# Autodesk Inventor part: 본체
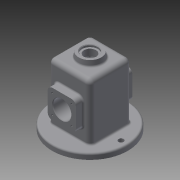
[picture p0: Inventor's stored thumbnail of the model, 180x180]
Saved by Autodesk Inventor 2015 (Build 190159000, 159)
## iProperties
Created: 2021-08
Part Number: 본체
Material: 일반
Document SubType Name: Modeling
Designer: 104589
Density: 1 g/cm^3
Appearance: 기본값
Mass: 304.335 g
Surface Area: 949.017 cm^2
Volume: 304.335 cm^3
Author: 104589
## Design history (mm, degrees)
sketch "스케치1"
  geometry: L1 (-37, -37)-(37, -37); L2 (37, -37)-(37, 37); L3 (37, 37)-(-37, 37); L4 (-37, 37)-(-37, -37); L5 (-37, -37)-(37, 37); L6 (37, -37)-(-37, 37); 1 further point
  constraints: 12 end point, 2 midpoint, 2 parallel, 1 horizontal, 1 perpendicular
  dimensions: "d0" = 74 distance of L2.end L3.end; "d1" = 74 distance of L1.end L2.end
extrude "돌출1" new body sketch "스케치1" distance "d2" = 100; taper "d3" = 0 deg
fillet "모깎기1" dims "d4" = 8
fillet "모깎기2" dims "d5" = 8
feature "쉘1" dims "d6" = 5
sketch "스케치3"
  geometry: L1 (-29, 32)-(29, 32) reference; L2 (32, 29)-(32, -29) reference; L3 (29, -32)-(-29, -32) reference; L4 (-32, -29)-(-32, 29) reference; C1 r 67 at (0, 0); A1 r 3 centre (-29, 29) between (-29, 32) and (-32, 29) reference; A2 r 3 centre (29, 29) between (32, 29) and (29, 32) reference; A3 r 3 centre (29, -29) between (29, -32) and (32, -29) reference; A4 r 3 centre (-29, -29) between (-32, -29) and (-29, -32) reference; 1 further point
  constraints: 1 centre point, 1 coincident
  dimensions: "d7" = 134 diameter of C1
extrude "돌출2" join sketch "스케치3" distance "d8" = 10; taper "d9" = 0 deg
sketch "스케치6"
  geometry: L1 (0, -92)-(58, -92) reference; L2 (4, -72)-(54, -72); L3 (54, -72)-(54, -22); L4 (54, -22)-(4, -22); L5 (4, -22)-(4, -72); L6 (4, -72)-(54, -22); L7 (54, -72)-(4, -22); L8 (-38, -102)-(96, -102) reference; 4 further points
  constraints: 12 end point, 4 midpoint, 2 parallel, 1 horizontal, 1 perpendicular, 1 vertical alignment
  dimensions: "d20" = 50 distance of L3.end L4.end; "d21" = 50 distance of L2.end L3.end; "d22" = 55 distance from line of point (29, -47) L8
extrude "돌출4" join sketch "스케치6" distance "d23" = 13; taper "d24" = 0 deg
sketch "스케치7"
  geometry: L1 (0, 102)-(58, 102) reference; C1 r 25 at (29, 47); 1 further point
  constraints: 1 centre point, 1 vertical alignment
  dimensions: "d25" = 55 distance from line of C1.centre L1; "d26" = 50 diameter of C1
extrude "돌출5" join sketch "스케치7" distance "d27" = 7; taper "d28" = -20 deg
sketch "스케치8"
  geometry: L1 (-38, -102)-(96, -102) reference; 2 further points
  constraints: 1 vertical alignment
  dimensions: "d29" = 55 distance from line of point (29, -47) L1
hole "구멍2" sketch "스케치8" at (29, -47) diameter "d30" = 32; stored, may be unused: countersink angle "d34" = 90 deg, drill point angle "d36" = 118 deg; dims "d31" = 6, "d32" = 4, "d33" = 2, "d35" = 8
fillet "모깎기3" dims "d37" = 8
fillet "모깎기4" dims "d38" = 8
sketch "스케치9"
  geometry: A1 r 8 centre (12, -64) between (4, -64) and (12, -72) reference; A2 r 8 centre (46, -64) between (46, -72) and (54, -64) reference; A3 r 8 centre (46, -30) between (54, -30) and (46, -22) reference; A4 r 8 centre (12, -30) between (12, -22) and (4, -30) reference; 1 further point
hole "구멍3" sketch "스케치9" at (46, -30), (12, -30), (12, -64), (46, -64) diameter "d39" = 3.242; stored, may be unused: countersink angle "d43" = 90 deg, drill point angle "d45" = 118 deg; dims "d40" = 8, "d41" = 4, "d42" = 2, "d44" = 10
fillet "모깎기5" dims "d46" = 3
chamfer "모따기1" distance "d47" = 1; stored, may be unused: second distance "d48" = 2, angle "d49" = 45 deg
sketch "스케치10"
  geometry: C1 r 67 at (0, 0) reference; A1 r 55 centre (0, 0) between (-55, 0) and (55, 0)
  constraints: 2 horizontal alignment, 2 point on circle, 1 centre point, 1 coincident
  dimensions: "d50" = 110 diameter of A1
hole "구멍4" sketch "스케치10" at (-55, 0), (55, 0) diameter "d51" = 9; stored, may be unused: countersink angle "d55" = 90 deg, drill point angle "d57" = 118 deg; dims "d52" = 8, "d53" = 4, "d54" = 2, "d56" = 10
fillet "모깎기6" dims "d58" = 3
sketch "스케치11"
  geometry: L1 (58, 102)-(0, 102) reference; L2 (9, -18)-(49, -18) reference; 3 further points
  constraints: 1 midpoint, 1 vertical alignment, 1 other
  dimensions: "d59" = 28 distance from line of point (29, 10) L2
feature "엠보싱1" sketch "스케치11" dims "d0" = 74, "d1" = 74, "d60" = 0.5, "d61" = 0
node "작업 평면1"
sketch "스케치12"
  geometry: C1 r 20 at (0, 0); 1 further point
  constraints: 1 centre point, 1 coincident
  dimensions: "d63" = 40 diameter of C1
extrude "돌출6" join sketch "스케치12" distance "d64" = 10; taper "d65" = 6 deg
sketch "스케치13"
  geometry: C1 r 20 at (0, 0) reference
hole "구멍5" sketch "스케치13" at (0, 0) diameter "d66" = 21; stored, may be unused: countersink angle "d70" = 90 deg, drill point angle "d72" = 118 deg; dims "d67" = 8, "d68" = 28, "d69" = 4, "d71" = 10
fillet "모깎기7" dims "d73" = 3
chamfer "모따기2" distance "d74" = 1; stored, may be unused: second distance "d75" = 2, angle "d76" = 45 deg
node "솔리드1"
mirror "대칭1"
mirror "대칭2"
